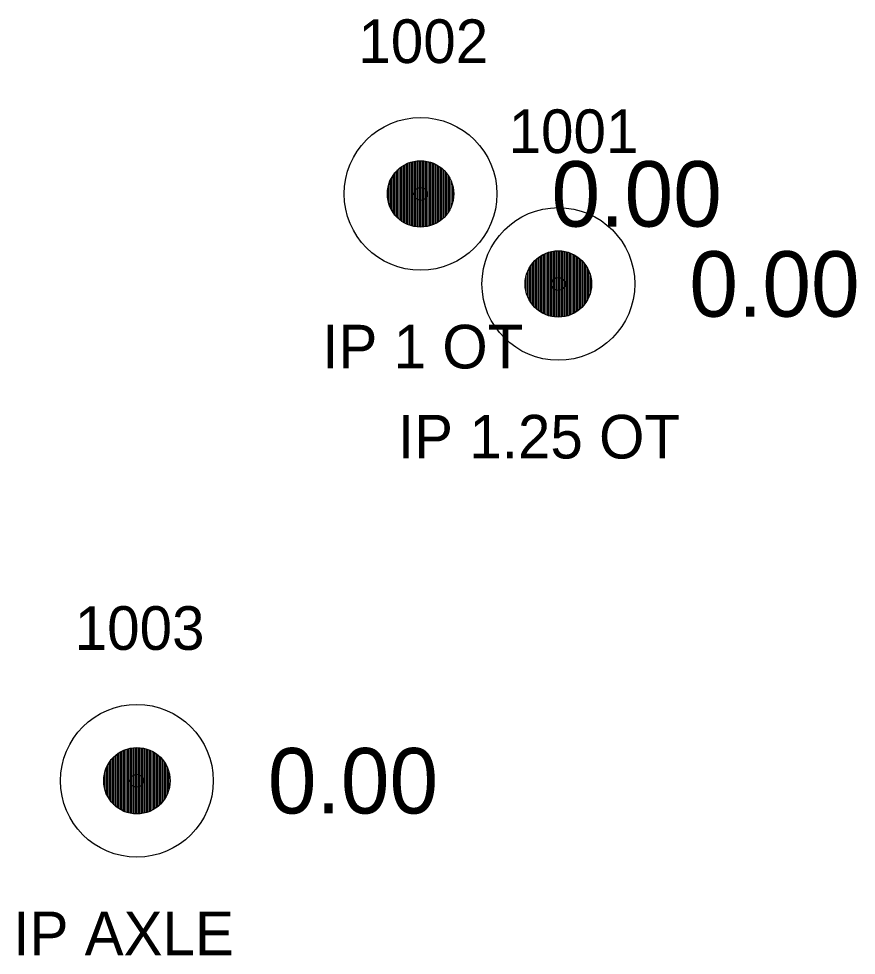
# Model space of a CAD drawing. Extents: x 1655137 to 1657928, y 1003994 to 1005407.
# Drawn here: x 1657908.88 to 1657928.07, y 1004762.11 to 1004783.57 of the extents above; entities that cross this region are included whole.
import ezdxf

# ---------------------------------------------------------------- set-up
doc = ezdxf.new("R2010")
doc.units = 0
for name, color, linetype in [('RD_EX_DV_Prop_txCode', 7, 'Continuous'), ('RD_EX_DV_PropPin', 7, 'Continuous'), ('RD_EX_TX_DV_Prop_ELEV', 7, 'Continuous'), ('RD_SMD_Locator', 7, 'Continuous')]:
    doc.layers.add(name, color=color, linetype=linetype)

msp = doc.modelspace()

# ---------------------------------------------------------------- linework, layer by layer
at = {"layer": 'RD_EX_DV_PropPin'}
for p, q in [((1657917.663, 1004778.923), (1657917.663, 1004780.192)), ((1657917.698, 1004778.901), (1657917.698, 1004780.213)), ((1657917.733, 1004778.881), (1657917.733, 1004780.233)), ((1657917.768, 1004778.864), (1657917.768, 1004780.25)), ((1657917.803, 1004778.85), (1657917.803, 1004780.265)), ((1657917.838, 1004778.837), (1657917.838, 1004780.278)), ((1657917.873, 1004778.826), (1657917.873, 1004780.289)), ((1657917.908, 1004778.816), (1657917.908, 1004780.298)), ((1657917.943, 1004778.809), (1657917.943, 1004780.305)), ((1657917.978, 1004778.803), (1657917.978, 1004780.311)), ((1657918.013, 1004778.799), (1657918.013, 1004780.315)), ((1657918.048, 1004778.797), (1657918.048, 1004780.317)), ((1657918.083, 1004778.796), (1657918.083, 1004780.318)), ((1657918.118, 1004778.797), (1657918.118, 1004780.317)), ((1657918.153, 1004778.799), (1657918.153, 1004780.315)), ((1657918.188, 1004778.803), (1657918.188, 1004780.311)), ((1657918.223, 1004778.809), (1657918.223, 1004780.305)), ((1657918.258, 1004778.816), (1657918.258, 1004780.298)), ((1657918.293, 1004778.826), (1657918.293, 1004780.289)), ((1657918.328, 1004778.837), (1657918.328, 1004780.278)), ((1657918.363, 1004778.85), (1657918.363, 1004780.265)), ((1657918.398, 1004778.864), (1657918.398, 1004780.25)), ((1657918.433, 1004778.881), (1657918.433, 1004780.233)), ((1657918.468, 1004778.901), (1657918.468, 1004780.213)), ((1657918.503, 1004778.923), (1657918.503, 1004780.192)), ((1657917.453, 1004779.131), (1657917.453, 1004779.984)), ((1657917.488, 1004779.083), (1657917.488, 1004780.031)), ((1657917.523, 1004779.042), (1657917.523, 1004780.072)), ((1657917.558, 1004779.006), (1657917.558, 1004780.108)), ((1657917.593, 1004778.975), (1657917.593, 1004780.139)), ((1657917.628, 1004778.947), (1657917.628, 1004780.167)), ((1657918.538, 1004778.947), (1657918.538, 1004780.167)), ((1657918.573, 1004778.975), (1657918.573, 1004780.139)), ((1657918.608, 1004779.006), (1657918.608, 1004780.108)), ((1657918.644, 1004779.042), (1657918.644, 1004780.072)), ((1657918.679, 1004779.083), (1657918.679, 1004780.031)), ((1657918.714, 1004779.131), (1657918.714, 1004779.984)), ((1657917.383, 1004779.259), (1657917.383, 1004779.855)), ((1657917.418, 1004779.188), (1657917.418, 1004779.927)), ((1657918.749, 1004779.188), (1657918.749, 1004779.927)), ((1657918.784, 1004779.259), (1657918.784, 1004779.855)), ((1657917.348, 1004779.361), (1657917.348, 1004779.753)), ((1657918.819, 1004779.361), (1657918.819, 1004779.753)), ((1657920.716, 1004776.942), (1657920.716, 1004778.043)), ((1657920.751, 1004776.91), (1657920.751, 1004778.075)), ((1657920.786, 1004776.883), (1657920.786, 1004778.102)), ((1657920.821, 1004776.858), (1657920.821, 1004778.127)), ((1657920.856, 1004776.836), (1657920.856, 1004778.149)), ((1657920.891, 1004776.817), (1657920.891, 1004778.168)), ((1657920.926, 1004776.8), (1657920.926, 1004778.185)), ((1657920.961, 1004776.785), (1657920.961, 1004778.2)), ((1657920.996, 1004776.772), (1657920.996, 1004778.213)), ((1657921.031, 1004776.761), (1657921.031, 1004778.224)), ((1657921.066, 1004776.752), (1657921.066, 1004778.233)), ((1657921.101, 1004776.745), (1657921.101, 1004778.241)), ((1657921.136, 1004776.739), (1657921.136, 1004778.246)), ((1657921.171, 1004776.735), (1657921.171, 1004778.25)), ((1657921.206, 1004776.732), (1657921.206, 1004778.253)), ((1657921.241, 1004776.732), (1657921.241, 1004778.254)), ((1657921.276, 1004776.732), (1657921.276, 1004778.253)), ((1657921.312, 1004776.735), (1657921.312, 1004778.25)), ((1657921.347, 1004776.739), (1657921.347, 1004778.246)), ((1657921.382, 1004776.745), (1657921.382, 1004778.241)), ((1657921.417, 1004776.752), (1657921.417, 1004778.233)), ((1657921.452, 1004776.761), (1657921.452, 1004778.224)), ((1657921.487, 1004776.772), (1657921.487, 1004778.213)), ((1657921.522, 1004776.785), (1657921.522, 1004778.2)), ((1657921.557, 1004776.8), (1657921.557, 1004778.185)), ((1657921.592, 1004776.817), (1657921.592, 1004778.168)), ((1657921.627, 1004776.836), (1657921.627, 1004778.149)), ((1657921.662, 1004776.858), (1657921.662, 1004778.127)), ((1657921.697, 1004776.883), (1657921.697, 1004778.102)), ((1657921.732, 1004776.91), (1657921.732, 1004778.075)), ((1657921.767, 1004776.942), (1657921.767, 1004778.043)), ((1657920.576, 1004777.123), (1657920.576, 1004777.862)), ((1657920.611, 1004777.066), (1657920.611, 1004777.919)), ((1657920.646, 1004777.018), (1657920.646, 1004777.967)), ((1657920.681, 1004776.978), (1657920.681, 1004778.008)), ((1657921.802, 1004776.978), (1657921.802, 1004778.008)), ((1657921.837, 1004777.018), (1657921.837, 1004777.967)), ((1657921.872, 1004777.066), (1657921.872, 1004777.919)), ((1657921.907, 1004777.123), (1657921.907, 1004777.862)), ((1657920.506, 1004777.296), (1657920.506, 1004777.689)), ((1657920.541, 1004777.195), (1657920.541, 1004777.791)), ((1657921.942, 1004777.195), (1657921.942, 1004777.791)), ((1657921.977, 1004777.296), (1657921.977, 1004777.689)), ((1657911.093, 1004765.525), (1657911.093, 1004766.689)), ((1657911.128, 1004765.497), (1657911.128, 1004766.717)), ((1657911.163, 1004765.473), (1657911.163, 1004766.742)), ((1657911.198, 1004765.451), (1657911.198, 1004766.764)), ((1657911.233, 1004765.432), (1657911.233, 1004766.783)), ((1657911.268, 1004765.415), (1657911.268, 1004766.8)), ((1657911.303, 1004765.4), (1657911.303, 1004766.815)), ((1657911.338, 1004765.387), (1657911.338, 1004766.828)), ((1657911.373, 1004765.376), (1657911.373, 1004766.839)), ((1657911.408, 1004765.367), (1657911.408, 1004766.848)), ((1657911.443, 1004765.359), (1657911.443, 1004766.855)), ((1657911.478, 1004765.354), (1657911.478, 1004766.861)), ((1657911.513, 1004765.35), (1657911.513, 1004766.865)), ((1657911.548, 1004765.347), (1657911.548, 1004766.868)), ((1657911.583, 1004765.346), (1657911.583, 1004766.868)), ((1657911.618, 1004765.347), (1657911.618, 1004766.868)), ((1657911.653, 1004765.35), (1657911.653, 1004766.865)), ((1657911.688, 1004765.354), (1657911.688, 1004766.861)), ((1657911.723, 1004765.359), (1657911.723, 1004766.855)), ((1657911.758, 1004765.367), (1657911.758, 1004766.848)), ((1657911.793, 1004765.376), (1657911.793, 1004766.839)), ((1657911.828, 1004765.387), (1657911.828, 1004766.828)), ((1657911.863, 1004765.4), (1657911.863, 1004766.815)), ((1657911.898, 1004765.415), (1657911.898, 1004766.8)), ((1657911.933, 1004765.432), (1657911.933, 1004766.783)), ((1657911.968, 1004765.451), (1657911.968, 1004766.764)), ((1657912.003, 1004765.473), (1657912.003, 1004766.742)), ((1657912.038, 1004765.497), (1657912.038, 1004766.717)), ((1657912.073, 1004765.525), (1657912.073, 1004766.689)), ((1657910.918, 1004765.738), (1657910.918, 1004766.477)), ((1657910.953, 1004765.681), (1657910.953, 1004766.534)), ((1657910.988, 1004765.633), (1657910.988, 1004766.581)), ((1657911.023, 1004765.592), (1657911.023, 1004766.622)), ((1657911.058, 1004765.557), (1657911.058, 1004766.658)), ((1657912.108, 1004765.557), (1657912.108, 1004766.658)), ((1657912.143, 1004765.592), (1657912.143, 1004766.622)), ((1657912.178, 1004765.633), (1657912.178, 1004766.581)), ((1657912.213, 1004765.681), (1657912.213, 1004766.534)), ((1657912.248, 1004765.738), (1657912.248, 1004766.477)), ((1657910.848, 1004765.911), (1657910.848, 1004766.303)), ((1657910.883, 1004765.809), (1657910.883, 1004766.405)), ((1657912.283, 1004765.809), (1657912.283, 1004766.405)), ((1657912.318, 1004765.911), (1657912.318, 1004766.303))]:
    msp.add_line(p, q, dxfattribs=at)
for centre, radius in [((1657918.083, 1004779.557), 1.75), ((1657918.083, 1004779.557), 0.761), ((1657921.241, 1004777.493), 1.75), ((1657921.241, 1004777.493), 0.761), ((1657911.583, 1004766.107), 1.75), ((1657911.583, 1004766.107), 0.761)]:
    msp.add_circle(centre, radius, dxfattribs=at)
at = {"layer": 'RD_SMD_Locator'}
for centre in [(1657918.083, 1004779.557), (1657921.242, 1004777.493), (1657911.583, 1004766.107)]:
    msp.add_circle(centre, 0.15, dxfattribs=at)

# ---------------------------------------------------------------- texts
at = {"layer": 'RD_EX_DV_Prop_txCode'}
for s, p in [('1002', (1657916.658, 1004782.557)), ('1001', (1657920.1, 1004780.493)), ('IP 1 OT', (1657915.831, 1004775.557)), ('IP 1.25 OT', (1657917.564, 1004773.493)), ('1003', (1657910.158, 1004769.107)), ('IP AXLE', (1657908.752, 1004762.107))]:
    msp.add_text(s, height=1, dxfattribs=at).set_placement(p)
at = {"layer": 'RD_EX_TX_DV_Prop_ELEV'}
for p in [(1657921.083, 1004778.807), (1657924.242, 1004776.743), (1657914.583, 1004765.357)]:
    msp.add_text('0.00', height=1.5, dxfattribs=at).set_placement(p)

doc.saveas('drawing.dxf')
